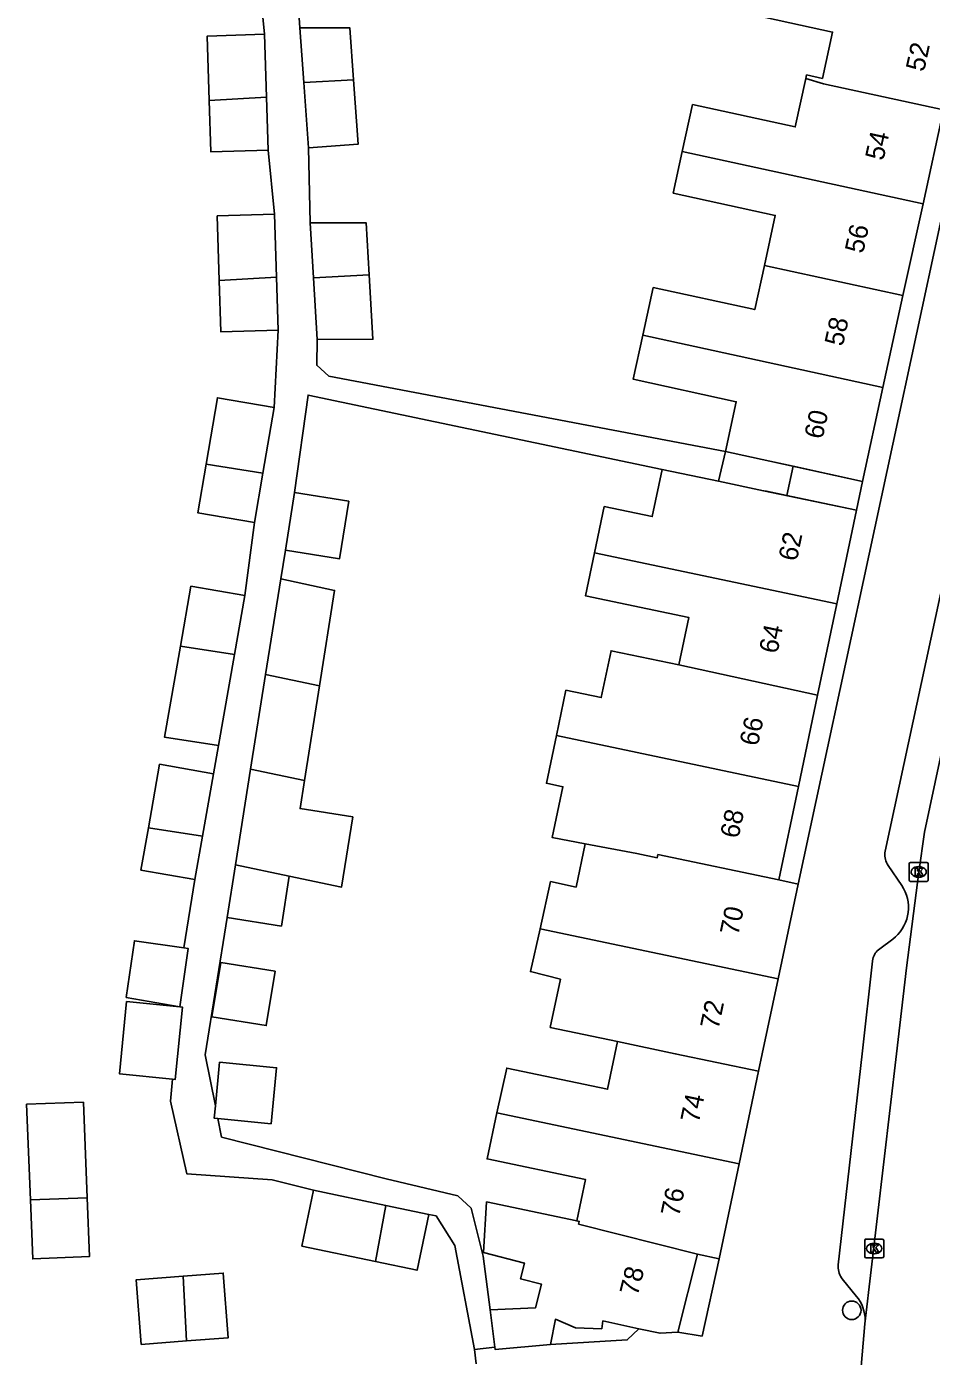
# Model space of a CAD drawing. Extents: x 160861 to 161308, y 384024 to 384878.
# Drawn here: x 161085.5 to 161133.2, y 384734 to 384804.2 of the extents above; entities that cross this region are included whole.
import ezdxf

# ---------------------------------------------------------------- set-up
doc = ezdxf.new("R2010")
doc.units = 0
for name, color, linetype in [('IMGEO_Boom', 7, 'Continuous'), ('IMGEO_Kolk', 7, 'Continuous'), ('IMGEO_Pand', 7, 'Continuous'), ('IMGEO_Pand_nummerreeks', 7, 'Continuous'), ('IMGEO_Pand_overbouw', 7, 'Continuous'), ('IMGEO_Rijbaan_lokaal_open', 7, 'Continuous'), ('IMGEO_Voetpad_open', 7, 'Continuous')]:
    doc.layers.add(name, color=color, linetype=linetype)

msp = doc.modelspace()

# ---------------------------------------------------------------- linework, layer by layer
at = {"layer": 'IMGEO_Boom'}
msp.add_circle((161128.979, 384736.468), 0.489, dxfattribs=at)
at = {"layer": 'IMGEO_Kolk'}
for p, q in [((161132.006, 384759.164), (161132.006, 384760.016)), ((161132.081, 384760.09), (161132.933, 384760.09)), ((161132.494, 384759.87), (161132.519, 384759.87)), ((161133.007, 384760.016), (161133.007, 384759.164)), ((161132.933, 384759.09), (161132.081, 384759.09)), ((161132.517, 384759.31), (161132.492, 384759.31)), ((161129.663, 384739.302), (161129.663, 384740.154)), ((161129.738, 384740.228), (161130.59, 384740.228)), ((161130.151, 384740.008), (161130.176, 384740.008)), ((161130.664, 384740.154), (161130.664, 384739.302)), ((161130.174, 384739.448), (161130.149, 384739.448)), ((161130.59, 384739.228), (161129.738, 384739.228))]:
    msp.add_line(p, q, dxfattribs=at)
for points in [[(161132.006, 384759.164), (161132.006, 384760.016)], [(161132.081, 384760.09), (161132.933, 384760.09)], [(161132.327, 384759.79), (161132.45, 384759.79), (161132.45, 384759.639), (161132.58, 384759.79), (161132.744, 384759.79), (161132.598, 384759.639), (161132.751, 384759.39), (161132.599, 384759.39), (161132.514, 384759.554), (161132.45, 384759.487), (161132.45, 384759.39), (161132.327, 384759.39), (161132.327, 384759.79)], [(161133.007, 384760.016), (161133.007, 384759.164)], [(161132.933, 384759.09), (161132.081, 384759.09)], [(161129.663, 384739.302), (161129.663, 384740.154)], [(161129.738, 384740.228), (161130.59, 384740.228)], [(161130.664, 384740.154), (161130.664, 384739.302)], [(161129.984, 384739.928), (161130.107, 384739.928), (161130.107, 384739.777), (161130.237, 384739.928), (161130.401, 384739.928), (161130.255, 384739.777), (161130.408, 384739.528), (161130.256, 384739.528), (161130.171, 384739.692), (161130.107, 384739.625), (161130.107, 384739.528), (161129.984, 384739.528), (161129.984, 384739.928)], [(161130.59, 384739.228), (161129.738, 384739.228)]]:
    msp.add_lwpolyline(points, dxfattribs=at)
for centre, start, end in [((161132.083, 384760.014), 91.55205, 178.44795), ((161132.083, 384760.014), 91.55205, 178.44795), ((161132.931, 384760.014), 1.55205, 88.44795), ((161132.931, 384760.014), 1.55205, 88.44795), ((161132.083, 384759.166), 181.55205, 268.44795), ((161132.083, 384759.166), 181.55205, 268.44795), ((161132.931, 384759.166), 271.55205, 358.44795), ((161132.931, 384759.166), 271.55205, 358.44795), ((161129.74, 384740.152), 91.55205, 178.44795), ((161129.74, 384740.152), 91.55205, 178.44795), ((161130.588, 384740.152), 1.55205, 88.44795), ((161130.588, 384740.152), 1.55205, 88.44795), ((161129.74, 384739.304), 181.55205, 268.44795), ((161129.74, 384739.304), 181.55205, 268.44795), ((161130.588, 384739.304), 271.55205, 358.44795), ((161130.588, 384739.304), 271.55205, 358.44795)]:
    msp.add_arc(centre, 0.0765, start, end, dxfattribs=at)
for centre, major_axis, ratio, start_param, end_param in [((161132.493, 384759.59), (-0.387, 0.002), 0.722429, 4.712389, 7.853982), ((161132.518, 384759.59), (-0.39, 0.002), 0.717154, 1.570796, 4.712389), ((161130.15, 384739.728), (-0.387, 0.002), 0.722429, 4.712389, 7.853982), ((161130.175, 384739.728), (-0.39, 0.002), 0.717154, 1.570796, 4.712389)]:
    msp.add_ellipse(centre, major_axis=major_axis, ratio=ratio, start_param=start_param, end_param=end_param, dxfattribs=at)
at = {"layer": 'IMGEO_Pand'}
for points in [[(161123.253, 384807.342), (161122.747, 384805.026), (161127.968, 384803.886), (161127.435, 384801.449), (161126.599, 384801.631), (161126.557, 384801.438)], [(161102.717, 384801.372), (161102.517, 384804.121), (161099.883, 384804.121)], [(161099.883, 384804.121), (161100.093, 384801.235)], [(161095.108, 384800.282), (161094.998, 384803.682), (161098.012, 384803.78)], [(161098.012, 384803.78), (161098.12, 384800.449)], [(161102.717, 384801.372), (161100.093, 384801.235)], [(161100.093, 384801.235), (161100.343, 384797.791)], [(161100.343, 384797.791), (161102.964, 384797.981), (161102.717, 384801.372)], [(161126.557, 384801.438), (161126, 384798.885), (161120.584, 384800.068), (161120.045, 384797.599)], [(161126.557, 384801.438), (161127.495, 384801.168), (161133.817, 384799.792)], [(161098.12, 384800.449), (161095.108, 384800.282)], [(161098.12, 384800.449), (161098.209, 384797.666)], [(161098.209, 384797.666), (161095.196, 384797.569), (161095.108, 384800.282)], [(161132.734, 384794.832), (161133.817, 384799.792)], [(161120.045, 384797.599), (161119.564, 384795.396), (161124.948, 384794.22), (161124.373, 384791.584)], [(161120.045, 384797.599), (161132.734, 384794.832)], [(161131.677, 384789.991), (161132.734, 384794.832)], [(161095.636, 384790.791), (161095.526, 384794.19), (161098.54, 384794.288)], [(161098.54, 384794.288), (161098.647, 384790.958)], [(161103.541, 384791.079), (161103.383, 384793.822), (161100.428, 384793.822)], [(161100.428, 384793.822), (161100.599, 384790.924)], [(161124.373, 384791.584), (161123.863, 384789.248), (161118.513, 384790.415), (161117.966, 384787.91)], [(161131.677, 384789.991), (161124.373, 384791.584)], [(161095.636, 384790.791), (161098.647, 384790.958)], [(161098.737, 384788.174), (161095.724, 384788.077), (161095.636, 384790.791)], [(161098.647, 384790.958), (161098.737, 384788.174)], [(161100.599, 384790.924), (161103.541, 384791.079)], [(161100.599, 384790.924), (161100.79, 384787.678)], [(161100.79, 384787.678), (161103.736, 384787.69), (161103.541, 384791.079)], [(161130.62, 384785.149), (161131.677, 384789.991)], [(161117.966, 384787.91), (161117.458, 384785.581), (161122.888, 384784.395), (161122.314, 384781.769)], [(161117.966, 384787.91), (161130.62, 384785.149)], [(161129.538, 384780.192), (161130.62, 384785.149)], [(161094.939, 384781.097), (161095.536, 384784.599), (161098.53, 384784.089)], [(161098.53, 384784.089), (161097.939, 384780.622)], [(161129.538, 384780.192), (161124.654, 384781.258), (161122.314, 384781.769)], [(161097.497, 384778.029), (161094.503, 384778.54), (161094.939, 384781.097)], [(161097.939, 384780.622), (161094.939, 384781.097)], [(161118.987, 384780.82), (161118.464, 384778.332), (161115.929, 384778.865), (161115.415, 384776.418)], [(161129.227, 384778.668), (161124.334, 384779.697), (161121.959, 384780.196), (161118.987, 384780.82)], [(161097.939, 384780.622), (161097.497, 384778.029)], [(161099.119, 384776.559), (161101.981, 384776.105), (161102.462, 384779.143), (161099.601, 384779.597)], [(161099.119, 384776.559), (161099.601, 384779.597)], [(161128.189, 384773.732), (161129.227, 384778.668)], [(161115.415, 384776.418), (161114.94, 384774.161), (161120.382, 384773.017), (161119.854, 384770.505)], [(161115.415, 384776.418), (161128.189, 384773.732)], [(161098.08, 384770.002), (161098.881, 384775.056)], [(161100.918, 384769.405), (161101.717, 384774.441), (161098.881, 384775.056)], [(161093.589, 384771.503), (161094.145, 384774.663), (161096.98, 384774.164)], [(161096.98, 384774.164), (161096.432, 384771.053)], [(161127.177, 384768.916), (161128.189, 384773.732)], [(161095.586, 384766.251), (161092.743, 384766.701), (161093.589, 384771.503)], [(161096.432, 384771.053), (161093.589, 384771.503)], [(161096.432, 384771.053), (161095.586, 384766.251)], [(161119.854, 384770.505), (161116.294, 384771.253), (161115.775, 384768.784), (161113.912, 384769.176), (161113.409, 384766.78)], [(161119.854, 384770.505), (161127.177, 384768.916)], [(161097.288, 384765.01), (161098.08, 384770.002)], [(161100.918, 384769.405), (161098.08, 384770.002)], [(161100.127, 384764.414), (161100.918, 384769.405)], [(161127.177, 384768.916), (161126.164, 384764.099)], [(161113.409, 384766.78), (161112.881, 384764.269), (161113.752, 384764.086), (161113.188, 384761.403), (161114.927, 384761.077)], [(161126.164, 384764.099), (161113.409, 384766.78)], [(161091.901, 384761.921), (161092.491, 384765.27), (161095.325, 384764.77)], [(161095.325, 384764.77), (161094.744, 384761.471)], [(161097.288, 384765.01), (161096.489, 384759.97)], [(161100.127, 384764.414), (161097.288, 384765.01)], [(161099.328, 384759.373), (161102.083, 384758.794), (161102.67, 384762.493), (161099.892, 384762.933), (161100.127, 384764.414)], [(161125.127, 384759.166), (161126.164, 384764.099)], [(161094.342, 384759.188), (161091.508, 384759.688), (161091.901, 384761.921)], [(161094.744, 384761.471), (161091.901, 384761.921)], [(161094.744, 384761.471), (161094.342, 384759.188)], [(161114.927, 384761.077), (161114.448, 384758.795), (161113.097, 384759.079), (161112.544, 384756.594)], [(161125.127, 384759.166), (161118.763, 384760.502), (161118.728, 384760.335), (161117.644, 384760.568), (161114.927, 384761.077)], [(161096.047, 384757.183), (161096.489, 384759.97)], [(161096.489, 384759.97), (161099.328, 384759.373)], [(161096.047, 384757.183), (161098.908, 384756.73), (161099.328, 384759.373)], [(161126.145, 384758.952), (161125.094, 384753.955)], [(161126.145, 384758.952), (161125.127, 384759.166)], [(161112.544, 384756.594), (161112.04, 384754.333), (161113.622, 384753.927), (161113.088, 384751.385), (161116.632, 384750.64)], [(161112.544, 384756.594), (161125.094, 384753.955)], [(161093.773, 384755.588), (161091.159, 384755.964), (161090.729, 384752.972), (161093.548, 384752.476)], [(161093.548, 384752.476), (161093.987, 384755.557), (161093.773, 384755.588)], [(161095.251, 384751.944), (161098.109, 384751.481), (161098.574, 384754.35), (161095.716, 384754.813), (161095.251, 384751.944)], [(161125.094, 384753.955), (161124.263, 384750), (161124.069, 384749.076)], [(161093.548, 384752.476), (161090.751, 384752.749), (161090.379, 384748.933), (161093.169, 384748.661)], [(161093.169, 384748.661), (161093.318, 384748.646), (161093.69, 384752.462), (161093.548, 384752.476)], [(161116.632, 384750.64), (161116.104, 384748.13), (161110.792, 384749.247), (161110.268, 384746.884)], [(161116.632, 384750.64), (161119.677, 384750), (161124.069, 384749.076)], [(161095.432, 384747.248), (161095.655, 384749.554), (161098.657, 384749.263), (161098.37, 384746.306), (161095.564, 384746.578)], [(161124.069, 384749.076), (161123.043, 384744.198)], [(161085.679, 384742.289), (161085.479, 384747.333), (161088.471, 384747.444), (161088.668, 384742.407)], [(161095.564, 384746.578), (161095.369, 384746.597), (161095.432, 384747.248)], [(161110.268, 384746.884), (161109.757, 384744.453), (161114.95, 384743.361), (161114.492, 384741.185)], [(161123.043, 384744.198), (161110.268, 384746.884)], [(161123.043, 384744.198), (161121.99, 384739.186)], [(161103.867, 384739.042), (161099.991, 384739.855), (161100.609, 384742.8)], [(161100.609, 384742.8), (161104.418, 384742.002)], [(161085.679, 384742.289), (161088.668, 384742.407)], [(161088.668, 384742.407), (161088.79, 384739.297), (161085.802, 384739.181), (161085.679, 384742.289)], [(161114.492, 384741.185), (161109.731, 384742.186), (161109.56, 384739.512), (161111.719, 384738.961), (161111.507, 384738.13), (161112.629, 384737.844), (161112.313, 384736.604), (161109.913, 384736.496)], [(161104.418, 384742.002), (161103.867, 384739.042)], [(161103.867, 384739.042), (161106.062, 384738.582), (161106.679, 384741.528)], [(161106.679, 384741.528), (161104.418, 384742.002)], [(161120.854, 384739.425), (161114.574, 384741.018), (161114.61, 384741.16), (161114.492, 384741.185)], [(161119.811, 384735.306), (161120.854, 384739.425)], [(161120.854, 384739.425), (161121.99, 384739.186)], [(161093.738, 384738.269), (161091.256, 384738.076), (161091.522, 384734.665), (161093.914, 384734.851)], [(161093.914, 384734.851), (161096.108, 384735.022), (161095.842, 384738.433), (161093.738, 384738.269)], [(161093.914, 384734.851), (161093.738, 384738.269)], [(161109.913, 384736.496), (161110.169, 384734.526)], [(161113.104, 384734.661), (161113.36, 384735.992), (161114.414, 384735.547), (161115.798, 384735.497), (161115.862, 384735.903), (161117.758, 384735.497)], [(161119.811, 384735.306), (161118.878, 384735.258), (161117.758, 384735.497)], [(161113.104, 384734.661), (161110.186, 384734.397), (161110.169, 384734.526)]]:
    msp.add_lwpolyline(points, dxfattribs=at)
at = {"layer": 'IMGEO_Pand_overbouw'}
for points in [[(161122.314, 384781.769), (161121.959, 384780.196), (161124.334, 384779.697), (161124.482, 384779.666), (161125.557, 384779.44), (161125.883, 384780.99), (161124.654, 384781.258)], [(161125.557, 384779.44), (161129.227, 384778.668), (161129.538, 384780.192), (161125.883, 384780.99)]]:
    msp.add_lwpolyline(points, close=True, dxfattribs=at)
at = {"layer": 'IMGEO_Rijbaan_lokaal_open'}
for points in [[(161144.864, 384818.229), (161132.813, 384761.681), (161132.507, 384759.586), (161131.86, 384754.533), (161131.333, 384750), (161129.676, 384735.749)], [(161128.787, 384725.541), (161129.676, 384735.749)]]:
    msp.add_lwpolyline(points, dxfattribs=at)
at = {"layer": 'IMGEO_Voetpad_open'}
for points in [[(161099.883, 384804.121), (161099.587, 384808.528)], [(161098.012, 384803.78), (161097.681, 384807.158)], [(161134.886, 384799.558), (161126.145, 384758.952)], [(161098.54, 384794.288), (161098.209, 384797.666)], [(161100.428, 384793.822), (161100.343, 384797.791)], [(161098.53, 384784.089), (161098.737, 384788.174)], [(161122.314, 384781.769), (161101.418, 384785.742), (161100.771, 384786.313), (161100.79, 384787.678)], [(161099.601, 384779.597), (161100.319, 384784.743), (161118.987, 384780.82)], [(161129.227, 384778.668), (161129.538, 384780.192)], [(161096.98, 384774.164), (161097.497, 384778.029)], [(161098.881, 384775.056), (161099.119, 384776.559)], [(161129.676, 384735.749), (161129.686, 384735.924), (161129.68, 384736.1), (161129.658, 384736.274), (161129.621, 384736.445), (161129.569, 384736.613), (161129.502, 384736.775), (161129.421, 384736.931), (161129.326, 384737.078), (161129.232, 384737.201), (161128.478, 384738.132), (161128.437, 384738.188), (161128.389, 384738.264), (161128.348, 384738.345), (161128.315, 384738.428), (161128.289, 384738.515), (161128.271, 384738.603), (161128.261, 384738.693), (161128.259, 384738.783), (161128.265, 384738.873), (161129.521, 384750), (161130.073, 384754.886), (161130.075, 384754.906), (161130.09, 384754.989), (161130.112, 384755.07), (161130.142, 384755.149), (161130.178, 384755.224), (161130.22, 384755.297), (161130.269, 384755.365), (161130.324, 384755.428), (161130.385, 384755.486), (161130.45, 384755.539), (161131.135, 384756.044), (161131.279, 384756.162), (161131.411, 384756.293), (161131.532, 384756.434), (161131.639, 384756.586), (161131.732, 384756.747), (161131.81, 384756.916), (161131.873, 384757.091), (161131.921, 384757.271), (161131.951, 384757.454), (161131.966, 384757.64), (161131.964, 384757.826), (161131.945, 384758.011), (161131.91, 384758.193), (161131.858, 384758.372), (161131.791, 384758.545), (161131.708, 384758.712), (161131.612, 384758.87), (161130.889, 384759.936), (161130.843, 384760.011), (161130.805, 384760.089), (161130.773, 384760.17), (161130.749, 384760.253), (161130.733, 384760.339), (161130.724, 384760.425), (161130.723, 384760.512), (161130.73, 384760.599), (161130.744, 384760.685), (161133.883, 384775.302)], [(161095.325, 384764.77), (161095.586, 384766.251)], [(161093.773, 384755.588), (161094.342, 384759.188)], [(161095.432, 384747.248), (161094.899, 384749.941), (161096.047, 384757.183)], [(161100.609, 384742.8), (161098.432, 384743.348), (161093.918, 384743.672), (161093.064, 384747.504), (161093.169, 384748.661)], [(161109.913, 384736.496), (161109.547, 384739.314), (161108.91, 384741.85), (161108.204, 384742.509), (161104.436, 384743.404), (161095.757, 384745.605), (161095.564, 384746.578)], [(161109.099, 384734.403), (161108.056, 384739.886), (161107.063, 384741.457), (161106.679, 384741.528)], [(161121.99, 384739.186), (161121.088, 384735.109), (161119.811, 384735.306)], [(161117.758, 384735.497), (161117.139, 384734.904), (161113.104, 384734.661)], [(161110.169, 384734.526), (161109.099, 384734.403)], [(161109.099, 384734.403), (161109.186, 384733.651)]]:
    msp.add_lwpolyline(points, dxfattribs=at)

# ---------------------------------------------------------------- texts
at = {"layer": 'IMGEO_Pand_nummerreeks'}
for s, rotation, p in [('52', 77.6856, (161132.788, 384801.76)), ('54', 77.68463, (161130.644, 384797.072)), ('56', 77.68463, (161129.574, 384792.172)), ('58', 77.68463, (161128.505, 384787.275)), ('60', 77.68463, (161127.436, 384782.375)), ('62', 78.12852, (161126.078, 384775.938)), ('64', 78.12733, (161125.054, 384771.064)), ('66', 78.12733, (161124.029, 384766.189)), ('68', 78.12733, (161123.005, 384761.316)), ('70', 78.12873, (161122.991, 384756.194)), ('72', 78.12873, (161121.95, 384751.246)), ('74', 78.12852, (161120.912, 384746.309)), ('76', 78.12873, (161119.873, 384741.366)), ('78', 75.79086, (161117.688, 384737.185))]:
    msp.add_text(s, height=1, rotation=rotation, dxfattribs=at).set_placement(p)

doc.saveas('drawing.dxf')
